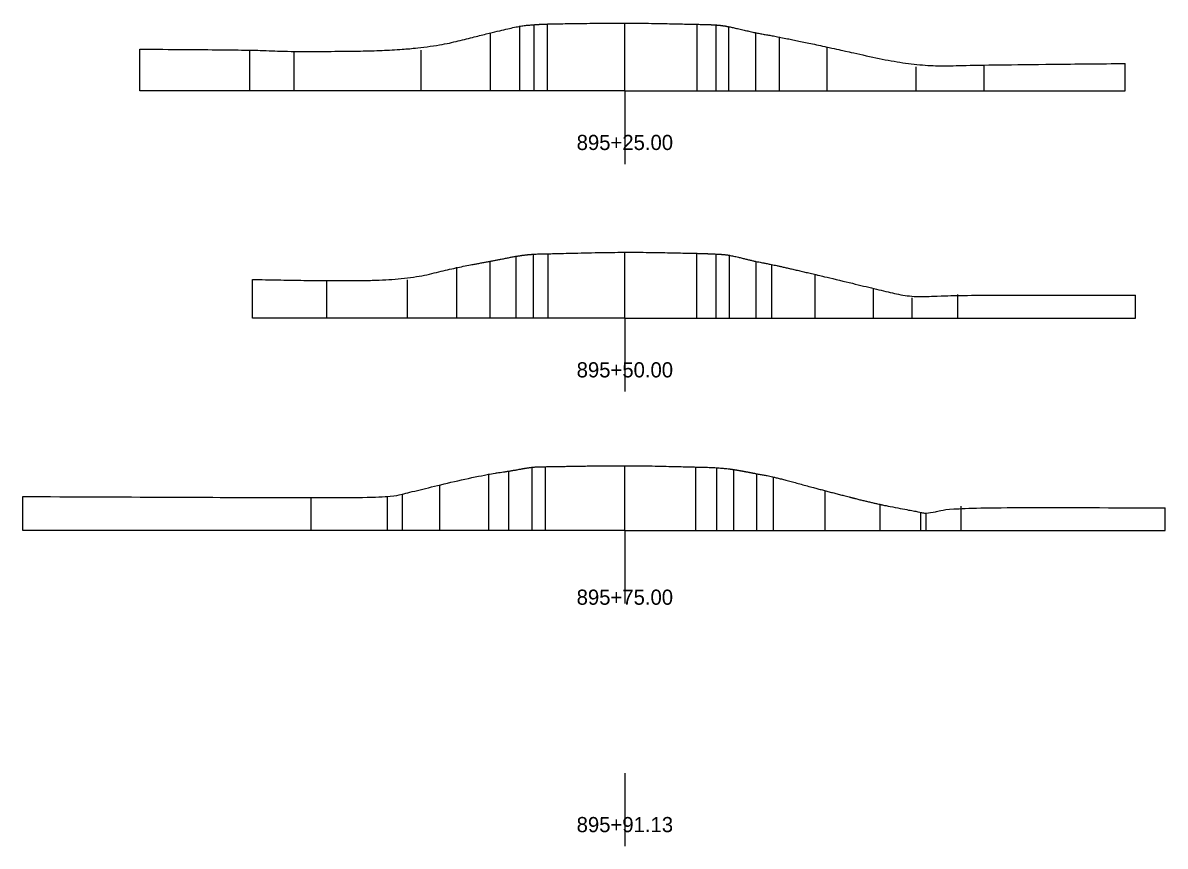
# Model space of a CAD drawing. Extents: x 1546689 to 1550004, y 741079 to 745265.
# Drawn here: x 1548204.05 to 1548241.72, y 743867.06 to 743894.22 of the extents above; entities that cross this region are included whole.
import ezdxf

# ---------------------------------------------------------------- set-up
doc = ezdxf.new("R2010")
doc.units = 0
doc.layers.add('UT_X_Electric_Cells', color=7, linetype='Continuous')
doc.layers.add('XS_P_Pavt_Layers', color=7, linetype='Continuous')

msp = doc.modelspace()

# ---------------------------------------------------------------- linework, layer by layer
at = {"layer": 'UT_X_Electric_Cells'}
for p, q in [((1548223.907, 743891.977), (1548223.907, 743889.564)), ((1548223.907, 743884.477), (1548223.907, 743882.064)), ((1548223.907, 743877.477), (1548223.907, 743875.064)), ((1548223.907, 743869.477), (1548223.907, 743867.064))]:
    msp.add_line(p, q, dxfattribs=at)
for points in [[(1548207.907, 743893.351), (1548211.54, 743893.336), (1548213.003, 743893.261), (1548217.191, 743893.319), (1548219.473, 743893.891), (1548220.441, 743894.119), (1548220.919, 743894.163), (1548221.353, 743894.187), (1548223.907, 743894.221), (1548226.293, 743894.175), (1548226.919, 743894.157), (1548227.329, 743894.103), (1548228.229, 743893.885), (1548229.007, 743893.755), (1548230.579, 743893.425), (1548233.507, 743892.771), (1548235.757, 743892.839), (1548240.407, 743892.879)], [(1548211.627, 743885.759), (1548214.077, 743885.701), (1548216.737, 743885.749), (1548218.359, 743886.157), (1548219.463, 743886.353), (1548220.323, 743886.529), (1548220.889, 743886.597), (1548221.375, 743886.603), (1548223.907, 743886.667), (1548226.273, 743886.621), (1548226.911, 743886.597), (1548227.353, 743886.567), (1548228.237, 743886.343), (1548228.757, 743886.253), (1548230.179, 743885.923), (1548232.107, 743885.463), (1548233.385, 743885.149), (1548234.883, 743885.259), (1548240.749, 743885.237)], [(1548204.051, 743878.597), (1548213.557, 743878.551), (1548216.075, 743878.575), (1548216.567, 743878.673), (1548217.801, 743878.985), (1548219.423, 743879.345), (1548220.079, 743879.429), (1548220.847, 743879.575), (1548221.287, 743879.581), (1548223.907, 743879.625), (1548226.245, 743879.571), (1548226.939, 743879.551), (1548227.501, 743879.493), (1548228.253, 743879.347), (1548228.809, 743879.251), (1548230.507, 743878.785), (1548232.325, 743878.323), (1548233.661, 743878.081), (1548233.839, 743878.027), (1548234.991, 743878.275), (1548241.723, 743878.219)]]:
    msp.add_open_spline(points, degree=2, dxfattribs=at)
at = {"layer": 'XS_P_Pavt_Layers'}
for p, q in [((1548223.907, 743891.977), (1548223.907, 743894.221)), ((1548223.907, 743884.477), (1548223.907, 743886.667)), ((1548223.907, 743877.477), (1548223.907, 743879.625))]:
    msp.add_line(p, q, dxfattribs=at)
for points in [[(1548223.907, 743891.977), (1548220.441, 743891.977), (1548220.441, 743894.119)], [(1548223.907, 743891.977), (1548220.919, 743891.977), (1548220.919, 743894.163)], [(1548223.907, 743891.977), (1548221.353, 743891.977), (1548221.353, 743894.187)], [(1548223.907, 743891.977), (1548226.293, 743891.977), (1548226.293, 743894.175)], [(1548223.907, 743891.977), (1548226.919, 743891.977), (1548226.919, 743894.157)], [(1548223.907, 743891.977), (1548227.329, 743891.977), (1548227.329, 743894.103)], [(1548223.907, 743891.977), (1548219.473, 743891.977), (1548219.473, 743893.891)], [(1548223.907, 743891.977), (1548228.229, 743891.977), (1548228.229, 743893.885)], [(1548223.907, 743891.977), (1548229.007, 743891.977), (1548229.007, 743893.755)], [(1548223.907, 743891.977), (1548207.907, 743891.977), (1548207.907, 743893.351)], [(1548223.907, 743891.977), (1548211.54, 743891.977), (1548211.54, 743893.336)], [(1548223.907, 743891.977), (1548213.003, 743891.977), (1548213.003, 743893.261)], [(1548223.907, 743891.977), (1548217.191, 743891.977), (1548217.191, 743893.319)], [(1548223.907, 743891.977), (1548230.579, 743891.977), (1548230.579, 743893.425)], [(1548223.907, 743891.977), (1548240.407, 743891.977), (1548240.407, 743892.879)], [(1548223.907, 743891.977), (1548235.757, 743891.977), (1548235.757, 743892.839)], [(1548223.907, 743891.977), (1548233.507, 743891.977), (1548233.507, 743892.771)], [(1548223.907, 743884.477), (1548220.323, 743884.477), (1548220.323, 743886.529)], [(1548223.907, 743884.477), (1548220.889, 743884.477), (1548220.889, 743886.597)], [(1548223.907, 743884.477), (1548221.375, 743884.477), (1548221.375, 743886.603)], [(1548223.907, 743884.477), (1548226.273, 743884.477), (1548226.273, 743886.621)], [(1548223.907, 743884.477), (1548226.911, 743884.477), (1548226.911, 743886.597)], [(1548223.907, 743884.477), (1548227.353, 743884.477), (1548227.353, 743886.567)], [(1548223.907, 743884.477), (1548218.359, 743884.477), (1548218.359, 743886.157)], [(1548223.907, 743884.477), (1548219.463, 743884.477), (1548219.463, 743886.353)], [(1548223.907, 743884.477), (1548228.237, 743884.477), (1548228.237, 743886.343)], [(1548223.907, 743884.477), (1548228.757, 743884.477), (1548228.757, 743886.253)], [(1548223.907, 743884.477), (1548211.627, 743884.477), (1548211.627, 743885.759)], [(1548223.907, 743884.477), (1548214.077, 743884.477), (1548214.077, 743885.701)], [(1548223.907, 743884.477), (1548216.737, 743884.477), (1548216.737, 743885.749)], [(1548223.907, 743884.477), (1548230.179, 743884.477), (1548230.179, 743885.923)], [(1548223.907, 743884.477), (1548232.107, 743884.477), (1548232.107, 743885.463)], [(1548223.907, 743884.477), (1548234.883, 743884.477), (1548234.883, 743885.259)], [(1548223.907, 743884.477), (1548240.749, 743884.477), (1548240.749, 743885.237)], [(1548223.907, 743884.477), (1548233.385, 743884.477), (1548233.385, 743885.149)], [(1548223.907, 743877.477), (1548219.423, 743877.477), (1548219.423, 743879.345)], [(1548223.907, 743877.477), (1548220.079, 743877.477), (1548220.079, 743879.429)], [(1548223.907, 743877.477), (1548220.847, 743877.477), (1548220.847, 743879.575)], [(1548223.907, 743877.477), (1548221.287, 743877.477), (1548221.287, 743879.581)], [(1548223.907, 743877.477), (1548226.245, 743877.477), (1548226.245, 743879.571)], [(1548223.907, 743877.477), (1548226.939, 743877.477), (1548226.939, 743879.551)], [(1548223.907, 743877.477), (1548227.501, 743877.477), (1548227.501, 743879.493)], [(1548223.907, 743877.477), (1548228.253, 743877.477), (1548228.253, 743879.347)], [(1548223.907, 743877.477), (1548228.809, 743877.477), (1548228.809, 743879.251)], [(1548223.907, 743877.477), (1548217.801, 743877.477), (1548217.801, 743878.985)], [(1548223.907, 743877.477), (1548204.051, 743877.477), (1548204.051, 743878.597)], [(1548223.907, 743877.477), (1548213.557, 743877.477), (1548213.557, 743878.551)], [(1548223.907, 743877.477), (1548216.075, 743877.477), (1548216.075, 743878.575)], [(1548223.907, 743877.477), (1548216.567, 743877.477), (1548216.567, 743878.673)], [(1548223.907, 743877.477), (1548230.507, 743877.477), (1548230.507, 743878.785)], [(1548223.907, 743877.477), (1548232.325, 743877.477), (1548232.325, 743878.323)], [(1548223.907, 743877.477), (1548234.991, 743877.477), (1548234.991, 743878.275)], [(1548223.907, 743877.477), (1548241.723, 743877.477), (1548241.723, 743878.219)], [(1548223.907, 743877.477), (1548233.661, 743877.477), (1548233.661, 743878.081)], [(1548223.907, 743877.477), (1548233.839, 743877.477), (1548233.839, 743878.027)]]:
    msp.add_lwpolyline(points, dxfattribs=at)

# ---------------------------------------------------------------- texts
at = {"layer": 'UT_X_Electric_Cells'}
for s, p in [('895+25.00', (1548222.315, 743890.026)), ('895+50.00', (1548222.315, 743882.526)), ('895+75.00', (1548222.315, 743875.026)), ('895+91.13', (1548222.315, 743867.526))]:
    msp.add_text(s, height=0.5, dxfattribs=at).set_placement(p)

doc.saveas('drawing.dxf')
